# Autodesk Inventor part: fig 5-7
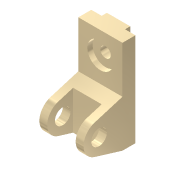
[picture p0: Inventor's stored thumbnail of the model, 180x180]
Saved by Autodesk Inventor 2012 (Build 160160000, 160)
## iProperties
Shininess: 65.0
Angle Display Precision: 2
Document Length Units: 11269
Document Angle Units: 11279
Document Time Units: 11290
Document Mass Units: 11283
Document Length Units Precision: 3
Document Angle Units Precision: 2
Compacted: False
Created: 2001-11
Part Number: fig 5-7
Document SubType Name: Modeling
Designer: Renu Muthoo
Density: 1 g/cm^3
Material: Default
Density: 0.0
Volumn: 0.0
Area: 0.0
PropertySet Name: Model Information
Control State: 0
Master: False
Checked Out: False
Author: Renu Muthoo
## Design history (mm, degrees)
node "Sketch1"
sketch "Sketch2"
  geometry: L1 (33.257, 104.664)-(33.257, -75.336); L2 (33.257, -75.336)-(8.257, -75.336); L3 (8.257, -75.336)-(-45.451, -59.045); L4 (-45.451, -1.628)-(8.257, 14.664); L5 (8.257, 14.664)-(8.257, 104.664); L6 (8.257, 104.664)-(33.257, 104.664); C1 r 15 at (-36.743, -30.336); A1 r 30 centre (-36.743, -30.336) between (-45.451, -1.628) and (-45.451, -59.045)
  constraints: 12 end point, 2 centre point, 2 equal length, 2 parallel, 2 point on circle, 2 tangent, 1 coincident, 1 perpendicular, 1 vertical
  dimensions: "d0" = 180 distance of L1.start L1.end; "d1" = 30 radius of A1; "d2" = 25 distance of L5.end L1.start; "d3" = 45 distance from line of L2 A1.centre; "d4" = 70 distance from line of L1 A1.centre; "d5" = 30 diameter of C1
extrude "Extrusion1" new body sketch "Sketch2" distance "d6" = 85; taper "d7" = 0 deg
workplane "Work Plane1"
sketch "Sketch3"
  geometry: L1 (15, 62.364)-(70, 62.364); L2 (70, 62.364)-(70, -52.386); L3 (70, -52.386)-(15, -52.386); L4 (15, -52.386)-(15, 62.364); L5 (0, -45)-(0, -28.708) reference
  constraints: 8 end point, 2 parallel, 1 horizontal, 1 perpendicular
  dimensions: "d8" = 55 distance of L1.start L1.end; "d9" = 15 distance between parallel lines of L5 L4
extrude "Extrusion2" cut sketch "Sketch3" distance "d10" = 50; taper "d11" = 0 deg
sketch "Sketch4"
  geometry: L1 (0, 25)-(85, 25) reference; L2 (0, 0)-(0, 25) reference; L3 (20, 25)-(65, 25); L4 (65, 25)-(65, 35); L5 (65, 35)-(20, 35); L6 (20, 35)-(20, 25)
  constraints: 8 end point, 2 parallel, 1 horizontal, 1 perpendicular, 1 point on line
  dimensions: "d12" = 45 distance of L4.end L5.end; "d13" = 10 distance of L3.end L4.end; "d14" = 20 distance between parallel lines of L2 L6
extrude "Extrusion3" join sketch "Sketch4" stored distance "d15" = 50; taper "d16" = 0 deg
sketch "Sketch5"
  geometry: L1 (85, 0)-(85, 90) reference; L2 (0, 90)-(85, 90) reference; 1 further point
  dimensions: "d17" = 42 distance from line of L2 point (42.5, 48); "d18" = 42.5 distance from line of L1 point (42.5, 48)
hole "Hole1" sketch "Sketch5" at (42.5, 48) diameter "d19" = 20; stored, may be unused: countersink angle "d23" = 82 deg, drill point angle "d25" = 118 deg; dims "d20" = 6, "d21" = 50, "d22" = 10, "d24" = 8
body "Solid1"
